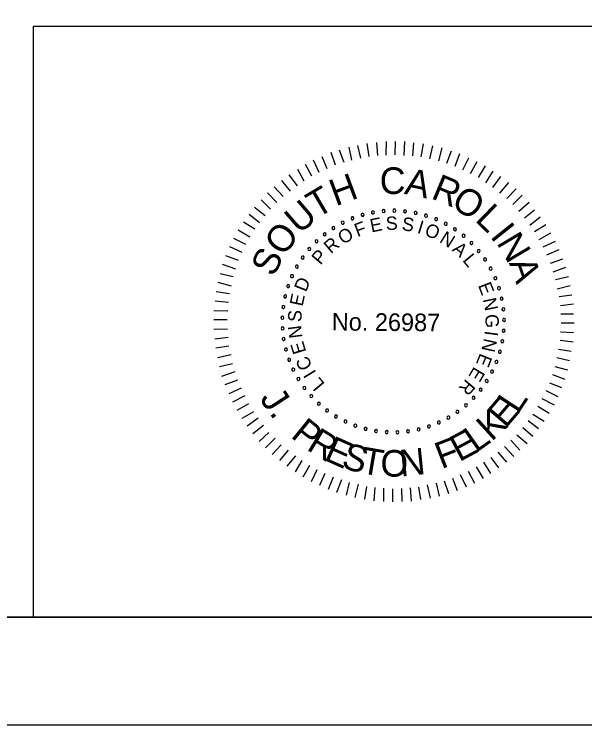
# Model space of a CAD drawing. Extents: x -125.5 to -89.4, y -5.1 to 16.9.
# Drawn here: x -102.989 to -100.335, y -5.066 to -1.761 of the extents above; entities that cross this region are included whole.
import ezdxf

# ---------------------------------------------------------------- set-up
doc = ezdxf.new("R2010")
doc.units = 0
for name, color, linetype in [('BR_BORDER LINES', 7, 'Continuous'), ('BR_TABLE LINES', 7, 'Continuous'), ('BR_TEXT', 7, 'Continuous'), ('Level 31', 7, 'Continuous')]:
    doc.layers.add(name, color=color, linetype=linetype)

msp = doc.modelspace()

# ---------------------------------------------------------------- linework, layer by layer
at = {"layer": 'BR_BORDER LINES'}
for p, q in [((-102.8989, -1.8161), (-97.5337, -1.8161)), ((-102.8989, -4.5661), (-102.8989, -1.8161)), ((-123.6994, -4.5662), (-90.0334, -4.5662))]:
    msp.add_line(p, q, dxfattribs=at)
at = {"layer": 'BR_TABLE LINES'}
msp.add_lwpolyline([(-123.6994, 16.4338), (-90.0334, 16.4338), (-90.0334, -4.5662), (-123.6994, -4.5662)], close=True, dxfattribs=at)
at = {"layer": 'BR_TEXT'}
for p, q in [((-101.418, -2.4404), (-101.4312, -2.3793)), ((-101.3767, -2.4304), (-101.3908, -2.3711)), ((-101.3372, -2.423), (-101.3461, -2.362)), ((-101.2977, -2.419), (-101.3015, -2.3581)), ((-101.2582, -2.4168), (-101.2576, -2.3524)), ((-101.2161, -2.4146), (-101.2156, -2.3528)), ((-101.1741, -2.4175), (-101.1718, -2.3531)), ((-101.1338, -2.4204), (-101.129, -2.3595)), ((-101.0952, -2.425), (-101.0844, -2.3642)), ((-101.0549, -2.4331), (-101.0407, -2.374)), ((-101.4937, -2.4629), (-101.5147, -2.4044)), ((-101.4541, -2.4504), (-101.476, -2.3927)), ((-101.0138, -2.4437), (-100.9979, -2.3829)), ((-100.977, -2.4543), (-100.9551, -2.397)), ((-100.9376, -2.4675), (-100.9157, -2.4093)), ((-101.5695, -2.4966), (-101.5957, -2.4406)), ((-101.5325, -2.4798), (-101.556, -2.4238)), ((-100.9017, -2.485), (-100.8738, -2.4294)), ((-101.604, -2.5144), (-101.6344, -2.46)), ((-100.8658, -2.5024), (-100.8345, -2.4469)), ((-100.8282, -2.5208), (-100.796, -2.467)), ((-101.6704, -2.5593), (-101.7095, -2.5083)), ((-101.6394, -2.5381), (-101.6698, -2.4838)), ((-100.795, -2.5451), (-100.761, -2.4913)), ((-101.7041, -2.5847), (-101.744, -2.5346)), ((-100.7617, -2.5668), (-100.7252, -2.5165)), ((-100.7293, -2.5928), (-100.6886, -2.5434)), ((-101.7369, -2.6094), (-101.7786, -2.5644)), ((-100.6977, -2.618), (-100.6545, -2.5737)), ((-101.7663, -2.6366), (-101.8106, -2.5925)), ((-100.6697, -2.6456), (-100.6264, -2.6022)), ((-101.7958, -2.6673), (-101.8392, -2.6248)), ((-100.6416, -2.6768), (-100.594, -2.6351)), ((-101.8209, -2.6988), (-101.8704, -2.6598)), ((-100.6144, -2.7088), (-100.5677, -2.6705)), ((-101.8469, -2.732), (-101.8964, -2.6922)), ((-100.5906, -2.7424), (-100.5414, -2.7033)), ((-101.8686, -2.761), (-101.9224, -2.728)), ((-100.5686, -2.7718), (-100.516, -2.7396)), ((-101.893, -2.7977), (-101.9467, -2.7656)), ((-101.9104, -2.8319), (-101.9668, -2.804)), ((-100.5466, -2.8089), (-100.4931, -2.7776)), ((-100.5288, -2.8433), (-100.4711, -2.8164)), ((-101.9279, -2.8687), (-101.9852, -2.8433)), ((-100.5111, -2.8804), (-100.4543, -2.856)), ((-101.9454, -2.9072), (-102.0035, -2.8852)), ((-100.4943, -2.9192), (-100.4374, -2.8982)), ((-101.9577, -2.9474), (-102.0193, -2.9246)), ((-100.4809, -2.9596), (-100.4232, -2.9378)), ((-101.97, -2.9833), (-102.0308, -2.9682)), ((-100.4708, -2.9957), (-100.4107, -2.9816)), ((-101.9772, -3.0253), (-102.0397, -3.0094)), ((-100.4626, -3.0378), (-100.4024, -3.0229)), ((-101.9878, -3.0613), (-102.0487, -3.0531)), ((-100.4543, -3.074), (-100.3951, -3.0667)), ((-101.9925, -3.1024), (-102.0542, -3.0951)), ((-100.4478, -3.1152), (-100.3868, -3.1088)), ((-101.9954, -3.1419), (-102.0597, -3.1414)), ((-100.4464, -3.1547), (-100.3863, -3.1552)), ((-101.9974, -3.183), (-102.06, -3.1825)), ((-100.4442, -3.1959), (-100.3833, -3.1964)), ((-101.9961, -3.226), (-102.0604, -3.2272)), ((-100.4471, -3.2388), (-100.3871, -3.241)), ((-101.9938, -3.2646), (-102.0556, -3.2718)), ((-100.4492, -3.2774), (-100.3883, -3.2856)), ((-101.9898, -3.3058), (-102.0509, -3.3148)), ((-100.4564, -3.3185), (-100.3972, -3.3284)), ((-101.9799, -3.3454), (-102.0426, -3.3586)), ((-100.4653, -3.3579), (-100.4053, -3.3721)), ((-101.9733, -3.3875), (-102.0344, -3.4016)), ((-100.4742, -3.3999), (-100.4143, -3.415)), ((-101.9616, -3.4245), (-102.0236, -3.4454)), ((-100.4848, -3.4367), (-100.4275, -3.4586)), ((-101.95, -3.4632), (-102.0085, -3.4842)), ((-101.9331, -3.5003), (-101.9908, -3.5272)), ((-100.4989, -3.4752), (-100.4424, -3.4971)), ((-100.5163, -3.512), (-100.4599, -3.5399)), ((-101.9162, -3.5364), (-101.9731, -3.566)), ((-100.5346, -3.5479), (-100.4774, -3.5784)), ((-101.8994, -3.5735), (-101.9537, -3.6048)), ((-100.553, -3.5846), (-100.5, -3.6168)), ((-101.8756, -3.6106), (-101.93, -3.6419)), ((-100.5756, -3.6213), (-100.5235, -3.6535)), ((-101.8544, -3.6399), (-101.9045, -3.6764)), ((-100.5981, -3.6503), (-100.5495, -3.6876)), ((-101.829, -3.6736), (-101.8791, -3.7127)), ((-100.6224, -3.6836), (-100.5764, -3.7234)), ((-101.8043, -3.7073), (-101.8485, -3.7481)), ((-101.7754, -3.7333), (-101.8204, -3.7784)), ((-100.6502, -3.7168), (-100.6033, -3.7584)), ((-101.7465, -3.7636), (-101.7889, -3.8095)), ((-100.6787, -3.7423), (-100.6362, -3.7882)), ((-101.714, -3.7895), (-101.7548, -3.8364)), ((-100.7392, -3.7976), (-100.6993, -3.8452)), ((-100.7073, -3.7721), (-100.6648, -3.8188)), ((-101.6808, -3.8156), (-101.7207, -3.8633)), ((-100.772, -3.8231), (-100.7364, -3.8714)), ((-101.6501, -3.8373), (-101.6814, -3.8894)), ((-101.6151, -3.8599), (-101.6464, -3.9137)), ((-100.8393, -3.8663), (-100.808, -3.9206)), ((-100.8057, -3.8443), (-100.7727, -3.8969)), ((-101.5809, -3.8799), (-101.608, -3.9355)), ((-101.5442, -3.8974), (-101.5687, -3.953)), ((-100.8773, -3.8857), (-100.8468, -3.9418)), ((-101.5057, -3.9149), (-101.5276, -3.9713)), ((-101.4663, -3.9272), (-101.4891, -3.9854)), ((-100.9892, -3.9311), (-100.9682, -3.9897)), ((-100.9496, -3.9194), (-100.9286, -3.9763)), ((-100.9135, -3.9026), (-100.8865, -3.9586)), ((-101.4304, -3.9395), (-101.4446, -3.9986)), ((-101.3892, -3.9467), (-101.4044, -4.0084)), ((-101.3499, -3.9582), (-101.3598, -4.0165)), ((-101.3104, -3.9628), (-101.3152, -4.0246)), ((-101.271, -3.9657), (-101.2715, -4.0275)), ((-101.1466, -3.9642), (-101.1428, -4.026)), ((-101.1079, -3.9602), (-101.098, -4.0186)), ((-101.0675, -3.9494), (-101.0542, -4.0113)), ((-101.0262, -3.9429), (-101.0112, -4.0022)), ((-101.229, -3.9686), (-101.2295, -4.0296)), ((-101.1869, -3.9664), (-101.1857, -4.0282))]:
    msp.add_line(p, q, dxfattribs=at)
for centre, start, end in [((-101.3196, -2.6831), 10.6038, 190.6038), ((-101.2702, -2.6764), 5.0653, 185.0653), ((-101.2702, -2.6764), 185.0653, 5.0653), ((-101.2204, -2.6745), 359.5268, 179.5268), ((-101.2204, -2.6745), 179.5268, 359.5268), ((-101.1707, -2.6774), 173.9884, 353.9884), ((-101.1707, -2.6774), 353.9884, 173.9884), ((-101.4153, -2.7106), 21.6807, 201.6807), ((-101.4153, -2.7106), 201.6807, 21.6807), ((-101.3681, -2.6945), 16.1422, 196.1422), ((-101.3681, -2.6945), 196.1422, 16.1422), ((-101.3196, -2.6831), 190.6038, 10.6038), ((-101.1214, -2.6851), 168.4499, 348.4499), ((-101.1214, -2.6851), 348.4499, 168.4499), ((-101.0732, -2.6976), 162.9114, 342.9114), ((-101.0732, -2.6976), 342.9114, 162.9114), ((-101.0263, -2.7146), 337.373, 157.373), ((-101.4607, -2.7311), 27.2191, 207.2191), ((-101.4607, -2.7311), 207.2191, 27.2191), ((-101.0263, -2.7146), 157.373, 337.373), ((-100.9814, -2.736), 151.8345, 331.8345), ((-100.9814, -2.736), 331.8345, 151.8345), ((-101.5039, -2.7559), 32.7576, 212.7576), ((-101.5039, -2.7559), 212.7576, 32.7576), ((-100.9387, -2.7617), 146.2961, 326.2961), ((-100.9387, -2.7617), 326.2961, 146.2961), ((-101.5445, -2.7848), 38.2961, 218.2961), ((-101.5445, -2.7848), 218.2961, 38.2961), ((-100.8987, -2.7914), 140.7576, 320.7576), ((-100.8987, -2.7914), 320.7576, 140.7576), ((-101.5821, -2.8175), 43.8345, 223.8345), ((-101.5821, -2.8175), 223.8345, 43.8345), ((-100.8617, -2.8249), 135.2191, 315.2191), ((-100.8617, -2.8249), 315.2191, 135.2191), ((-101.6164, -2.8536), 49.373, 229.373), ((-101.6164, -2.8536), 229.373, 49.373), ((-100.8282, -2.8617), 129.6807, 309.6807), ((-100.8282, -2.8617), 309.6807, 129.6807), ((-101.6471, -2.8929), 54.9114, 234.9114), ((-101.6471, -2.8929), 234.9114, 54.9114), ((-100.7983, -2.9016), 124.1422, 304.1422), ((-100.7983, -2.9016), 304.1422, 124.1422), ((-101.6738, -2.935), 60.4499, 240.4499), ((-101.6738, -2.935), 240.4499, 60.4499), ((-100.7724, -2.9442), 118.6038, 298.6038), ((-100.7724, -2.9442), 298.6038, 118.6038), ((-101.6964, -2.9794), 65.9884, 245.9884), ((-101.6964, -2.9794), 245.9884, 65.9884), ((-100.7508, -2.9891), 113.0653, 293.0653), ((-100.7508, -2.9891), 293.0653, 113.0653), ((-101.7145, -3.0258), 71.5268, 251.5268), ((-101.7145, -3.0258), 251.5268, 71.5268), ((-100.7336, -3.0359), 107.5268, 287.5268), ((-100.7336, -3.0359), 287.5268, 107.5268), ((-101.7281, -3.0738), 77.0653, 257.0653), ((-101.7281, -3.0738), 257.0653, 77.0653), ((-100.721, -3.0841), 101.9884, 281.9884), ((-100.721, -3.0841), 281.9884, 101.9884), ((-101.737, -3.1228), 82.6038, 262.6038), ((-101.737, -3.1228), 262.6038, 82.6038), ((-100.7131, -3.1333), 96.4499, 276.4499), ((-100.7131, -3.1333), 276.4499, 96.4499), ((-101.7411, -3.1724), 88.1422, 268.1422), ((-101.7411, -3.1724), 268.1422, 88.1422), ((-100.71, -3.183), 90.9114, 270.9114), ((-100.71, -3.183), 270.9114, 90.9114), ((-101.7404, -3.2223), 93.6807, 273.6807), ((-101.7404, -3.2223), 273.6807, 93.6807), ((-100.7118, -3.2328), 85.373, 265.373), ((-100.7118, -3.2328), 265.373, 85.373), ((-101.7349, -3.2718), 99.2191, 279.2191), ((-101.7349, -3.2718), 279.2191, 99.2191), ((-100.7183, -3.2822), 79.8345, 259.8345), ((-100.7183, -3.2822), 259.8345, 79.8345), ((-101.7246, -3.3206), 104.7576, 284.7576), ((-101.7246, -3.3206), 284.7576, 104.7576), ((-100.7295, -3.3308), 74.2961, 254.2961), ((-100.7295, -3.3308), 254.2961, 74.2961), ((-101.7097, -3.3681), 110.2961, 290.2961), ((-101.7097, -3.3681), 290.2961, 110.2961), ((-100.7454, -3.378), 68.7576, 248.7576), ((-100.7454, -3.378), 248.7576, 68.7576), ((-101.6903, -3.414), 115.8345, 295.8345), ((-101.6903, -3.414), 295.8345, 115.8345), ((-100.7658, -3.4235), 63.2191, 243.2191), ((-100.7658, -3.4235), 243.2191, 63.2191), ((-101.6665, -3.4578), 121.373, 301.373), ((-101.6665, -3.4578), 301.373, 121.373), ((-100.7904, -3.4668), 57.6807, 237.6807), ((-100.7904, -3.4668), 237.6807, 57.6807), ((-101.6386, -3.4991), 126.9114, 306.9114), ((-101.6386, -3.4991), 306.9114, 126.9114), ((-100.8192, -3.5075), 52.1422, 232.1422), ((-100.8192, -3.5075), 232.1422, 52.1422), ((-101.6069, -3.5375), 132.4499, 312.4499), ((-101.6069, -3.5375), 312.4499, 132.4499), ((-101.5716, -3.5727), 137.9884, 317.9884), ((-101.5716, -3.5727), 317.9884, 137.9884), ((-100.8517, -3.5452), 46.6038, 226.6038), ((-100.8517, -3.5452), 226.6038, 46.6038), ((-101.5331, -3.6043), 143.5268, 323.5268), ((-101.5331, -3.6043), 323.5268, 143.5268), ((-100.8877, -3.5797), 41.0653, 221.0653), ((-100.8877, -3.5797), 221.0653, 41.0653), ((-101.4917, -3.632), 149.0653, 329.0653), ((-101.4917, -3.632), 329.0653, 149.0653), ((-100.9688, -3.6374), 29.9884, 209.9884), ((-100.9688, -3.6374), 209.9884, 29.9884), ((-100.9269, -3.6105), 35.5268, 215.5268), ((-100.9269, -3.6105), 215.5268, 35.5268), ((-101.4478, -3.6556), 154.6038, 334.6038), ((-101.4478, -3.6556), 334.6038, 154.6038), ((-101.4018, -3.6749), 340.1422, 160.1422), ((-101.0132, -3.6601), 24.4499, 204.4499), ((-101.0132, -3.6601), 204.4499, 24.4499), ((-101.4018, -3.6749), 160.1422, 340.1422), ((-101.3542, -3.6896), 165.6807, 345.6807), ((-101.3542, -3.6896), 345.6807, 165.6807), ((-101.3054, -3.6997), 351.2191, 171.2191), ((-101.3054, -3.6997), 171.2191, 351.2191), ((-101.2559, -3.705), 356.7576, 176.7576), ((-101.2061, -3.7055), 2.2961, 182.2961), ((-101.1564, -3.7012), 7.8345, 187.8345), ((-101.1564, -3.7012), 187.8345, 7.8345), ((-101.1074, -3.6921), 13.373, 193.373), ((-101.1074, -3.6921), 193.373, 13.373), ((-101.0595, -3.6784), 18.9114, 198.9114), ((-101.0595, -3.6784), 198.9114, 18.9114), ((-101.2559, -3.705), 176.7576, 356.7576), ((-101.2061, -3.7055), 182.2961, 2.2961)]:
    msp.add_arc(centre, 0.00701, start, end, dxfattribs=at)
at = {"layer": 'Level 31'}
msp.add_lwpolyline([(-125.5328, -5.0661), (-89.5328, -5.0661), (-89.5328, 16.9339), (-125.5328, 16.9339)], close=True, dxfattribs=at)

# ---------------------------------------------------------------- texts
at = {"layer": 'BR_TEXT'}
for s, height, rotation, p in [('C', 0.1241, 359.5482, (-101.2889, -2.5969)), ('H', 0.1241, 20.3637, (-101.4933, -2.6552)), ('A', 0.1241, 348.1981, (-101.1775, -2.5961)), ('R', 0.1241, 337.4344, (-101.0542, -2.616)), ('T', 0.1241, 30.4992, (-101.5812, -2.7128)), ('O', 0.1239, 326.5869, (-100.962, -2.6528)), ('U', 0.1241, 40.8022, (-101.6624, -2.7875)), ('L', 0.1241, 315.9488, (-100.8494, -2.7205)), ('E', 0.0622, 11.4103, (-101.3269, -2.7764)), ('S', 0.0622, 2.208, (-101.2591, -2.7654)), ('S', 0.0622, 352.6608, (-101.1878, -2.7657)), ('O', 0.1241, 52.0267, (-101.7369, -2.8914)), ('F', 0.0622, 20.6127, (-101.392, -2.7981)), ('I', 0.0622, 343.1136, (-101.1175, -2.7777)), ('O', 0.0622, 338.4392, (-101.0841, -2.7878)), ('I', 0.1241, 308.6613, (-100.778, -2.7948)), ('O', 0.0622, 30.8477, (-101.4594, -2.8341)), ('N', 0.0622, 328.2042, (-101.0145, -2.8192)), ('N', 0.1241, 300.7037, (-100.7474, -2.8242)), ('R', 0.0622, 40.3949, (-101.5156, -2.878)), ('A', 0.0622, 318.657, (-100.9555, -2.8592)), ('S', 0.1239, 63.2511, (-101.7823, -2.9871)), ('P', 0.0622, 49.9421, (-101.5636, -2.9306)), ('L', 0.0622, 309.4546, (-100.9057, -2.9066)), ('A', 0.1241, 289.4792, (-100.6882, -2.9172)), ('D', 0.0622, 69.0364, (-101.6306, -3.0559)), ('E', 0.0622, 291.049, (-100.8319, -3.0219)), ('E', 0.0622, 78.2388, (-101.6472, -3.1226)), ('N', 0.0622, 281.8466, (-100.8097, -3.0869)), ('S', 0.0622, 87.786, (-101.6529, -3.1936)), ('No. 26987', 0.08175, 359.5268, (-101.5118, -3.232)), ('G', 0.0622, 272.2995, (-100.7979, -3.1572)), ('N', 0.0622, 97.3332, (-101.6467, -3.2646)), ('I', 0.0622, 262.4084, (-100.7983, -3.231)), ('E', 0.0622, 106.5355, (-101.6297, -3.3312)), ('N', 0.0622, 257.7339, (-100.8028, -3.2656)), ('C', 0.0622, 116.4266, (-101.5998, -3.3987)), ('E', 0.0622, 248.1867, (-100.8209, -3.3346)), ('E', 0.0622, 238.9844, (-100.8488, -3.3973)), ('I', 0.0622, 121.1011, (-101.5818, -3.4285)), ('L', 0.0622, 129.9595, (-101.5411, -3.4807)), ('R', 0.0622, 229.782, (-100.8865, -3.4548)), ('J', 0.1236, 302.9559, (-101.849, -3.5492)), ('E', 0.1236, 49.3639, (-100.703, -3.6911)), ('L', 0.1236, 56.4247, (-100.6455, -3.6233)), ('K', 0.1236, 42.3031, (-100.7683, -3.7512)), ('.', 0.1236, 309.3974, (-101.8049, -3.6172)), ('P', 0.1236, 321.1035, (-101.7065, -3.7264)), ('R', 0.1236, 328.5359, (-101.6332, -3.7844)), ('E', 0.1236, 28.1814, (-100.9186, -3.8452)), ('L', 0.1236, 35.2422, (-100.8406, -3.8028)), ('E', 0.1236, 335.9684, (-101.5531, -3.8325)), ('F', 0.1236, 21.1206, (-101.0013, -3.8776)), ('S', 0.1236, 343.0292, (-101.4718, -3.8682)), ('T', 0.1236, 350.4617, (-101.3821, -3.8947)), ('O', 0.1236, 358.1419, (-101.2867, -3.9097)), ('N', 0.1236, 5.8221, (-101.1902, -3.9118))]:
    msp.add_text(s, height=height, rotation=rotation, dxfattribs=at).set_placement(p)

doc.saveas('drawing.dxf')
